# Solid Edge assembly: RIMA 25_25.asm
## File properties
Title: Zylinder
Author: ahadarics
Template: iso metric assembly.asm
Last saved by: ahadarics
Revision: 5
Application: Solid Edge
Username: ahadarics
Dokumentum tartalom típus: 1
Document Number: RIMA 25/25
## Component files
Profilrohr.par
Kolbenstange.par
Kit_1.par
Kit_2.par
Mutter_1.par
Mutter_2.par
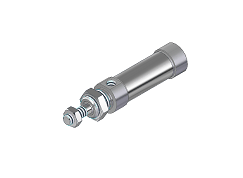
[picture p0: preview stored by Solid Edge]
